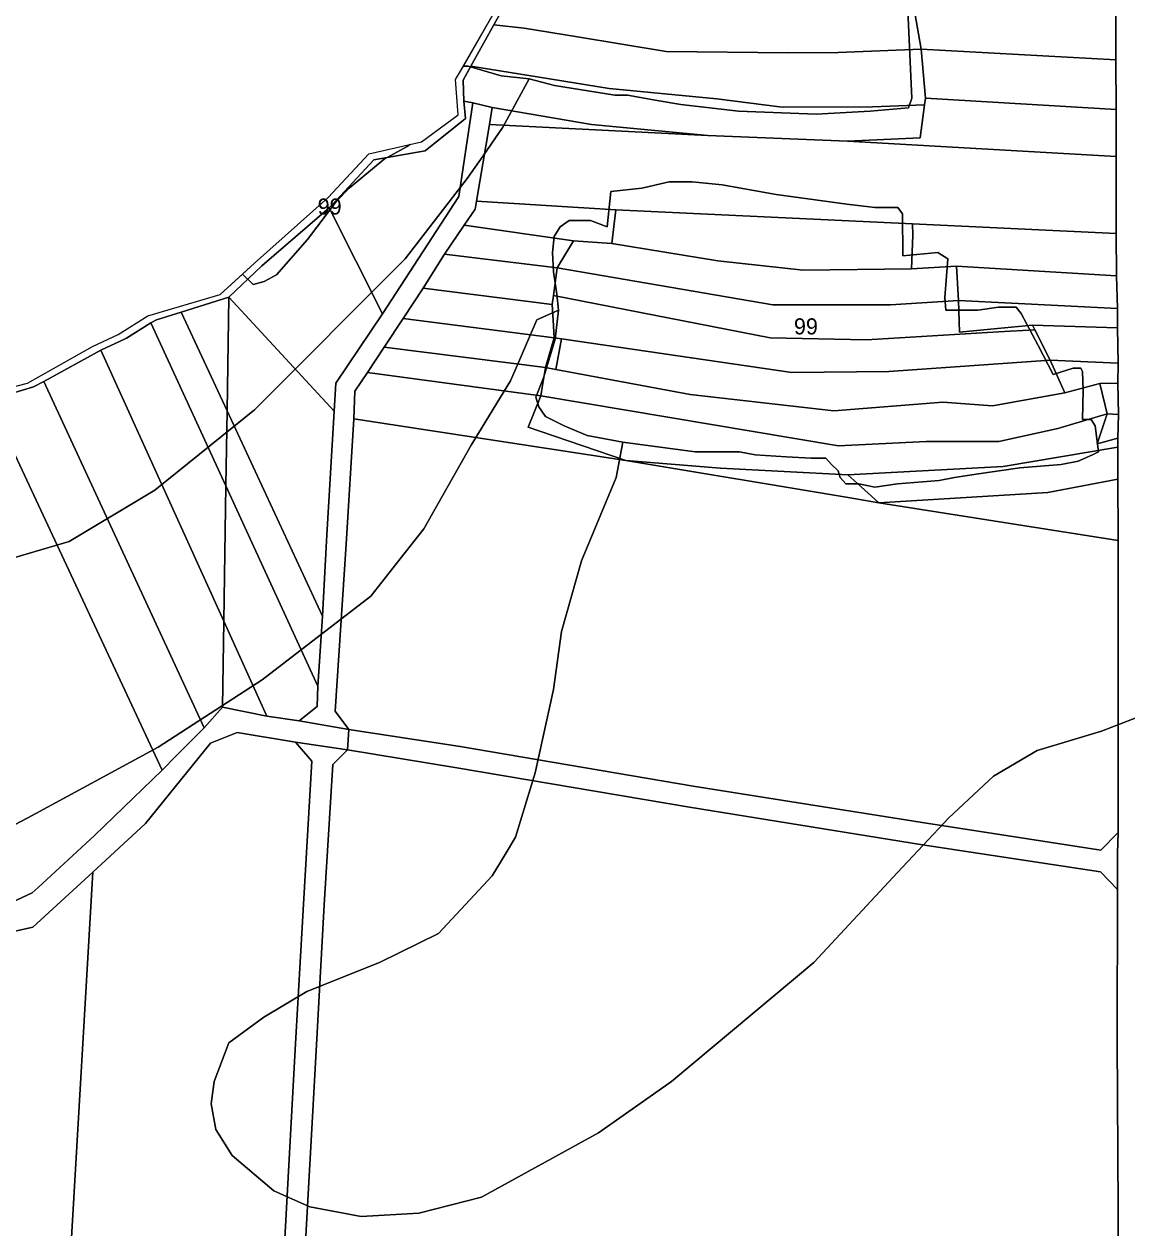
# Model space of a CAD drawing. Extents: x -541351 to -537540, y -1162694 to -1159725.
# Drawn here: x -541076 to -540733, y -1161202.6 to -1160827.9 of the extents above; entities that cross this region are included whole.
import ezdxf

# ---------------------------------------------------------------- set-up
doc = ezdxf.new("R2010")
doc.units = 0
for name, color, linetype in [('95560013', 7, 'Continuous'), ('95600013', 7, 'Continuous'), ('95610013', 7, 'Continuous'), ('95620013', 7, 'Continuous'), ('95630013', 7, 'Continuous'), ('95640013', 7, 'Continuous'), ('95660013', 7, 'Continuous')]:
    doc.layers.add(name, color=color, linetype=linetype)

msp = doc.modelspace()

# ---------------------------------------------------------------- linework, layer by layer
at = {"layer": '95560013'}
for points in [[(-541012.89, -1160948.29), (-541027.18, -1160917.57), (-541012.34, -1160912.92)], [(-540981.95, -1160988.78), (-540983.19, -1161012.15), (-541012.89, -1160948.29), (-541012.34, -1160912.92), (-540979.53, -1160948.34)], [(-541012.89, -1160948.29), (-541013.26, -1160971.68), (-541036.57, -1160920.93), (-541034.8, -1160920), (-541027.18, -1160917.57)], [(-541013.92, -1161013.74), (-541052.16, -1160929.36), (-541044.6, -1160925.92), (-541044.18, -1160925.64), (-541036.57, -1160920.93), (-541013.26, -1160971.68)], [(-541019.98, -1161046.9), (-541069.85, -1160939.12), (-541052.16, -1160929.36), (-541013.92, -1161013.74), (-541014.34, -1161040.54)], [(-541033.05, -1161060.07), (-541086.85, -1160944.98), (-541073.08, -1160940.82), (-541069.85, -1160939.12), (-541019.98, -1161046.9), (-541028.84, -1161055.79)], [(-541131.65, -1161018.53), (-541153.86, -1160970.54), (-541147.43, -1160967.41), (-541135.11, -1160960.45), (-541129.26, -1160956.98), (-541115.54, -1160952.68), (-541099.59, -1160950.61), (-541086.85, -1160944.98), (-541033.05, -1161060.07), (-541054.13, -1161080.42), (-541071.61, -1161096.64), (-541073.5, -1161098.28), (-541084.97, -1161103.63), (-541094.05, -1161099.67)], [(-541013.26, -1160971.68), (-541012.89, -1160948.29), (-540983.19, -1161012.15), (-540984.63, -1161034)], [(-540810.09, -1160976.9), (-540735.73, -1160988.61), (-540735.68, -1161079.51), (-540741.03, -1161085), (-540795.29, -1161076.62), (-540867.88, -1161065.11), (-540940.39, -1161052.8), (-540975.03, -1161047.45), (-540979.3, -1161041.8), (-540975.83, -1160989.77), (-540973.46, -1160950.74), (-540888.86, -1160963.71), (-540819.65, -1160975.28)], [(-541000.52, -1161043.31), (-541013.92, -1161013.74), (-541013.26, -1160971.68), (-540984.63, -1161034), (-540984.89, -1161040.3), (-540990.48, -1161044.81)], [(-541013.92, -1161013.74), (-541000.52, -1161043.31), (-541014.34, -1161040.54)], [(-541002.5, -1161335.95), (-541008.05, -1161340.22), (-541068.49, -1161330.02), (-541054.64, -1161091.86), (-541038.24, -1161076.76), (-541018.02, -1161051.7), (-541009.77, -1161048.36), (-540991.57, -1161051.36), (-540986.52, -1161057.36), (-540989.14, -1161101.78), (-540991.75, -1161147.06), (-540996.64, -1161238.13), (-541001.01, -1161309.69)], [(-540941.46, -1161059.38), (-540975.41, -1161053.82), (-540975.03, -1161047.45), (-540940.39, -1161052.8), (-540867.88, -1161065.11), (-540795.29, -1161076.62), (-540741.03, -1161085), (-540735.68, -1161079.51), (-540735.9, -1161086), (-540735.93, -1161097.29), (-540741.17, -1161091.8), (-540796.53, -1161083.37), (-540869, -1161071.68)], [(-540986.52, -1161057.36), (-540991.57, -1161051.36), (-540975.41, -1161053.82), (-540979.98, -1161058.32), (-540982.72, -1161102.03), (-540985.21, -1161147.42), (-540989.12, -1161218.21), (-540990.18, -1161238.48), (-540990.23, -1161238.98), (-540994.49, -1161310.1), (-540996.06, -1161337.06), (-540991.27, -1161343.31), (-541002.57, -1161341.19), (-541008.05, -1161340.22), (-541002.5, -1161335.95), (-541001.01, -1161309.69), (-540996.64, -1161238.13), (-540991.75, -1161147.06), (-540989.14, -1161101.78)], [(-540741.17, -1161091.8), (-540735.93, -1161097.29), (-540736, -1161144.39), (-540735.68, -1161196.89), (-540735.74, -1161259.49), (-540989.12, -1161218.21), (-540985.21, -1161147.42), (-540982.72, -1161102.03), (-540979.98, -1161058.32), (-540975.41, -1161053.82), (-540941.46, -1161059.38), (-540869, -1161071.68), (-540796.53, -1161083.37)], [(-541091.62, -1161326.12), (-541095.8, -1161325.34), (-541083.35, -1161111.3), (-541073.3, -1161109.03), (-541054.64, -1161091.86), (-541068.49, -1161330.02)]]:
    msp.add_lwpolyline(points, close=True, dxfattribs=at)
at = {"layer": '95600013'}
msp.add_lwpolyline([(-540736.3, -1160869.17), (-540736.28, -1160893.08), (-540799.66, -1160890.04), (-540891.91, -1160885.78), (-540935.25, -1160883), (-540931.25, -1160859.15), (-540863.38, -1160862.63), (-540819.89, -1160864.31)], close=True, dxfattribs=at)
at = {"layer": '95610013'}
for points in [[(-540798.89, -1160824.47), (-540783.37, -1160820.48), (-540764.18, -1160818.28), (-540736.36, -1160819.57), (-540736.43, -1160839.07), (-540797, -1160835.7)], [(-540795.64, -1160851.02), (-540797, -1160835.7), (-540736.43, -1160839.07), (-540736.28, -1160854.47)], [(-540951.26, -1160867.4), (-540938.73, -1160857.26), (-540939.2, -1160851.88), (-540936.46, -1160852.48), (-540940.84, -1160881.54), (-540964.49, -1160918.11), (-540981.17, -1160885.14), (-540980.33, -1160884.28), (-540967.24, -1160870.15)], [(-540736.3, -1160869.17), (-540819.89, -1160864.31), (-540797.32, -1160863.3), (-540795.91, -1160853.02), (-540795.64, -1160851.02), (-540736.28, -1160854.47)], [(-541002.06, -1160903.18), (-540981.17, -1160885.14), (-540964.49, -1160918.11), (-540979.01, -1160939.67), (-540979.53, -1160948.34), (-541012.34, -1160912.92)], [(-540939.11, -1160890.53), (-540905.15, -1160895.35), (-540910.19, -1160903.8), (-540945.23, -1160899.55)], [(-540951.85, -1160910.12), (-540945.23, -1160899.55), (-540910.19, -1160903.8), (-540911.33, -1160912.35), (-540911.72, -1160915.24)], [(-540785.33, -1160913.91), (-540785.97, -1160903.3), (-540736.22, -1160906.29), (-540735.86, -1160916.47)], [(-540911.72, -1160915.24), (-540911.45, -1160920.09), (-540911.15, -1160925.59), (-540958.07, -1160919.54), (-540951.85, -1160910.12)], [(-540773.18, -1160922.67), (-540785, -1160923.82), (-540785.33, -1160913.91), (-540735.86, -1160916.47), (-540735.87, -1160922.42), (-540762.31, -1160921.62)], [(-540958.07, -1160919.54), (-540911.15, -1160925.59), (-540911.97, -1160928.4), (-540913.85, -1160934.84), (-540963.99, -1160928.45)], [(-540761.61, -1160923.03), (-540762.31, -1160921.62), (-540735.87, -1160922.42), (-540735.69, -1160933.41), (-540756.88, -1160932.5)], [(-540915.07, -1160942.26), (-540915.29, -1160943.61), (-540969.18, -1160936.31), (-540963.99, -1160928.45), (-540913.85, -1160934.84)], [(-540735.79, -1160939.71), (-540741.43, -1160939.83), (-540752.32, -1160942.65), (-540756.88, -1160932.5), (-540735.69, -1160933.41)], [(-540973.46, -1160950.74), (-540973.09, -1160942.2), (-540969.18, -1160936.31), (-540915.29, -1160943.61), (-540919.24, -1160953.34), (-540915.61, -1160954.58), (-540888.86, -1160963.71)], [(-540741.43, -1160939.83), (-540735.79, -1160939.71), (-540735.59, -1160949.41), (-540739.08, -1160949.21)], [(-540739.08, -1160949.21), (-540735.59, -1160949.41), (-540735.79, -1160956.76), (-540742.25, -1160958.57)]]:
    msp.add_lwpolyline(points, close=True, dxfattribs=at)
at = {"layer": '95620013'}
for points in [[(-540838.25, -1160836.9), (-540876.25, -1160836.44), (-540903.88, -1160831.84), (-540920.43, -1160829.18), (-540929.88, -1160828.15), (-540927.39, -1160823.69), (-540919.49, -1160815.78), (-540908.47, -1160819.38), (-540899.74, -1160824.18), (-540849.08, -1160823.76), (-540803, -1160823.08), (-540783.37, -1160820.48), (-540798.89, -1160824.47), (-540797, -1160835.7), (-540822.78, -1160836.73)], [(-540915.84, -1160844.43), (-540937.08, -1160841.04), (-540929.88, -1160828.15), (-540920.43, -1160829.18), (-540903.88, -1160831.84), (-540876.25, -1160836.44), (-540838.25, -1160836.9), (-540822.78, -1160836.73), (-540797, -1160835.7), (-540795.64, -1160851.02), (-540795.91, -1160853.02), (-540812.07, -1160853.63), (-540840.21, -1160853.82), (-540860.48, -1160851.17), (-540894.06, -1160847.92)], [(-540840.21, -1160853.82), (-540812.07, -1160853.63), (-540795.91, -1160853.02), (-540797.32, -1160863.3), (-540819.89, -1160864.31), (-540863.38, -1160862.63), (-540899.55, -1160859.19), (-540930.39, -1160853.92), (-540936.46, -1160852.48), (-540939.2, -1160851.88), (-540939.48, -1160845.34), (-540937.08, -1160841.04), (-540915.84, -1160844.43), (-540894.06, -1160847.92), (-540860.48, -1160851.17)], [(-540899.55, -1160859.19), (-540863.38, -1160862.63), (-540931.25, -1160859.15), (-540930.39, -1160853.92)], [(-540935.25, -1160883), (-540891.91, -1160885.78), (-540893.16, -1160896.25), (-540905.15, -1160895.35), (-540939.11, -1160890.53), (-540935.75, -1160885.53)], [(-540833.7, -1160904.56), (-540860.25, -1160901.65), (-540893.16, -1160896.25), (-540891.91, -1160885.78), (-540799.66, -1160890.04), (-540799.6, -1160893.65), (-540799.98, -1160904.1)], [(-540736.28, -1160893.08), (-540736.22, -1160906.29), (-540785.97, -1160903.3), (-540799.98, -1160904.1), (-540799.6, -1160893.65), (-540799.66, -1160890.04)], [(-540910.19, -1160903.8), (-540905.15, -1160895.35), (-540893.16, -1160896.25), (-540860.25, -1160901.65), (-540833.7, -1160904.56), (-540799.98, -1160904.1), (-540785.97, -1160903.3), (-540785.33, -1160913.91), (-540806.46, -1160915.3), (-540843.14, -1160915.3)], [(-540843.91, -1160925.54), (-540911.33, -1160912.35), (-540910.19, -1160903.8), (-540843.14, -1160915.3), (-540806.46, -1160915.3), (-540785.33, -1160913.91), (-540785, -1160923.82), (-540773.18, -1160922.67), (-540762.31, -1160921.62), (-540761.61, -1160923.03), (-540772.92, -1160923.72), (-540813.93, -1160926.24)], [(-540843.91, -1160925.54), (-540813.93, -1160926.24), (-540772.92, -1160923.72), (-540761.61, -1160923.03), (-540756.88, -1160932.5), (-540807.02, -1160936.09), (-540837.23, -1160936.32), (-540908.89, -1160925.92), (-540911.15, -1160925.59), (-540911.45, -1160920.09), (-540911.72, -1160915.24), (-540911.33, -1160912.35)], [(-540910.59, -1160935.45), (-540913.85, -1160934.84), (-540911.97, -1160928.4), (-540911.15, -1160925.59), (-540908.89, -1160925.92)], [(-540807.02, -1160936.09), (-540756.88, -1160932.5), (-540752.32, -1160942.65), (-540774.82, -1160946.75), (-540790.27, -1160945.58), (-540824.11, -1160948.27), (-540868.84, -1160943.23), (-540910.59, -1160935.45), (-540908.89, -1160925.92), (-540837.23, -1160936.32)], [(-540739.08, -1160949.21), (-540754.44, -1160953.78), (-540772.83, -1160957.88), (-540795.43, -1160957.88), (-540822.71, -1160959.17), (-540915.29, -1160943.61), (-540915.07, -1160942.26), (-540913.85, -1160934.84), (-540910.59, -1160935.45), (-540868.84, -1160943.23), (-540824.11, -1160948.27), (-540790.27, -1160945.58), (-540774.82, -1160946.75), (-540752.32, -1160942.65), (-540741.43, -1160939.83)], [(-540771.43, -1160965.63), (-540819.8, -1160968.21), (-540859.38, -1160966.13), (-540888.86, -1160963.71), (-540915.61, -1160954.58), (-540919.24, -1160953.34), (-540915.29, -1160943.61), (-540822.71, -1160959.17), (-540795.43, -1160957.88), (-540772.83, -1160957.88), (-540754.44, -1160953.78), (-540739.08, -1160949.21), (-540742.25, -1160958.57), (-540735.79, -1160956.76), (-540735.79, -1160959.64)], [(-540816.82, -1160970.88), (-540819.8, -1160968.21), (-540771.43, -1160965.63), (-540735.79, -1160959.64), (-540735.78, -1160969.51), (-540757.53, -1160973.71), (-540810.09, -1160976.9)], [(-540888.86, -1160963.71), (-540859.38, -1160966.13), (-540819.8, -1160968.21), (-540816.82, -1160970.88), (-540810.09, -1160976.9), (-540819.65, -1160975.28)], [(-540735.73, -1160988.61), (-540810.09, -1160976.9), (-540757.53, -1160973.71), (-540735.78, -1160969.51), (-540735.72, -1160987.66)]]:
    msp.add_lwpolyline(points, close=True, dxfattribs=at)
at = {"layer": '95630013'}
for points in [[(-541088.68, -1160943.22), (-541074.96, -1160939.7), (-541054.72, -1160928.23), (-541046.74, -1160924.48), (-541037.53, -1160918.75), (-541015.05, -1160912.07), (-541004.31, -1160902.35), (-540981.39, -1160881.88), (-540968.74, -1160868.27), (-540952.45, -1160864.6), (-540941.04, -1160856.18), (-540941.79, -1160845.2), (-540929.37, -1160823.59)], [(-540927.39, -1160823.69), (-540929.88, -1160828.15), (-540937.08, -1160841.04), (-540939.48, -1160845.34), (-540939.2, -1160851.88), (-540938.73, -1160857.26), (-540951.26, -1160867.4), (-540967.24, -1160870.15), (-540980.33, -1160884.28), (-540981.17, -1160885.14), (-541002.06, -1160903.18), (-541012.34, -1160912.92), (-541027.18, -1160917.57), (-541034.8, -1160920), (-541036.57, -1160920.93), (-541044.18, -1160925.64), (-541044.6, -1160925.92), (-541052.16, -1160929.36), (-541069.85, -1160939.12), (-541073.08, -1160940.82), (-541086.85, -1160944.98)]]:
    msp.add_lwpolyline(points, dxfattribs=at)
at = {"layer": '95640013'}
for points in [[(-540735.74, -1161259.49), (-540735.68, -1161196.89), (-540736, -1161144.39), (-540735.93, -1161097.29), (-540735.9, -1161086), (-540735.68, -1161079.51), (-540735.73, -1160988.61), (-540735.72, -1160987.66), (-540735.78, -1160969.51), (-540735.79, -1160959.64), (-540735.79, -1160956.76), (-540735.59, -1160949.41), (-540735.79, -1160939.71), (-540735.69, -1160933.41), (-540735.87, -1160922.42), (-540735.86, -1160916.47), (-540736.22, -1160906.29), (-540736.28, -1160893.08), (-540736.3, -1160869.17), (-540736.28, -1160854.47), (-540736.43, -1160839.07), (-540736.36, -1160819.57)], [(-541084.97, -1161103.63), (-541073.5, -1161098.28), (-541071.61, -1161096.64), (-541054.13, -1161080.42), (-541033.05, -1161060.07), (-541028.84, -1161055.79), (-541019.98, -1161046.9), (-541014.34, -1161040.54), (-541000.52, -1161043.31), (-540990.48, -1161044.81), (-540975.03, -1161047.45), (-540975.41, -1161053.82), (-540991.57, -1161051.36), (-541009.77, -1161048.36), (-541018.02, -1161051.7), (-541038.24, -1161076.76), (-541054.64, -1161091.86), (-541073.3, -1161109.03), (-541083.35, -1161111.3)]]:
    msp.add_lwpolyline(points, dxfattribs=at)
msp.add_lwpolyline([(-540936.46, -1160852.48), (-540930.39, -1160853.92), (-540931.25, -1160859.15), (-540935.25, -1160883), (-540935.75, -1160885.53), (-540939.11, -1160890.53), (-540945.23, -1160899.55), (-540951.85, -1160910.12), (-540958.07, -1160919.54), (-540963.99, -1160928.45), (-540969.18, -1160936.31), (-540973.09, -1160942.2), (-540973.46, -1160950.74), (-540975.83, -1160989.77), (-540979.3, -1161041.8), (-540975.03, -1161047.45), (-540990.48, -1161044.81), (-540984.89, -1161040.3), (-540984.63, -1161034), (-540983.19, -1161012.15), (-540981.95, -1160988.78), (-540979.53, -1160948.34), (-540979.01, -1160939.67), (-540964.49, -1160918.11), (-540940.84, -1160881.54)], close=True, dxfattribs=at)
at = {"layer": '95660013'}
for points in [[(-541089.62, -1160997), (-541062, -1160989), (-541035.37, -1160973), (-541004.37, -1160948), (-540957.5, -1160901), (-540938.19, -1160876), (-540933.27, -1160868.89), (-540927.12, -1160860), (-540918.87, -1160845), (-540911, -1160847), (-540892.31, -1160850), (-540888.37, -1160850), (-540879.1, -1160851.67), (-540871.69, -1160853), (-540853.81, -1160855), (-540829.62, -1160856), (-540812.87, -1160855), (-540800.87, -1160854), (-540799.87, -1160851), (-540801.37, -1160819)], [(-540801.37, -1160819), (-540799.87, -1160851), (-540800.87, -1160854), (-540812.87, -1160855), (-540829.62, -1160856), (-540853.81, -1160855), (-540871.69, -1160853), (-540879.1, -1160851.67), (-540888.37, -1160850), (-540892.31, -1160850), (-540911, -1160847), (-540918.87, -1160845), (-540927.62, -1160844), (-540937.87, -1160841), (-540939.38, -1160841), (-540929.37, -1160823.59)], [(-541088.68, -1160943.22), (-541074.96, -1160939.7), (-541054.72, -1160928.23), (-541046.74, -1160924.48), (-541037.53, -1160918.75), (-541015.05, -1160912.07), (-541008.06, -1160905.75), (-541004.81, -1160909), (-541001.31, -1160908), (-540997.5, -1160906), (-540987.87, -1160895), (-540978.87, -1160883), (-540974.87, -1160879), (-540964, -1160870), (-540956.81, -1160866), (-540956.04, -1160865.41), (-540952.45, -1160864.6), (-540941.04, -1160856.18), (-540941.79, -1160845.2), (-540939.38, -1160841), (-540937.87, -1160841), (-540927.62, -1160844), (-540918.87, -1160845), (-540927.12, -1160860), (-540933.27, -1160868.89), (-540938.19, -1160876), (-540957.5, -1160901), (-541004.37, -1160948), (-541035.37, -1160973), (-541062, -1160989), (-541089.62, -1160997)], [(-540715.19, -1161038), (-540740.87, -1161048), (-540760.87, -1161054), (-540774.5, -1161062), (-540788.37, -1161075), (-540804.31, -1161092), (-540830.37, -1161120), (-540874.62, -1161157), (-540897.31, -1161173), (-540933.69, -1161193), (-540953.19, -1161198), (-540971.19, -1161199), (-540987.12, -1161196), (-540998.37, -1161191), (-541011.31, -1161180), (-541016.37, -1161172), (-541017.87, -1161164), (-541016.87, -1161157), (-541012.31, -1161145), (-541001.5, -1161137), (-540988.12, -1161129), (-540965.5, -1161120), (-540947.12, -1161111), (-540930.37, -1161093), (-540926.38, -1161086.33), (-540923.19, -1161081), (-540917, -1161061), (-540911.37, -1161035), (-540908.81, -1161017), (-540902.62, -1160995), (-540891.81, -1160969), (-540889.81, -1160958), (-540867.31, -1160961), (-540853.5, -1160961), (-540848.62, -1160962), (-540838.94, -1160962.56), (-540831.19, -1160963), (-540826.62, -1160963), (-540824.87, -1160965), (-540822.81, -1160967), (-540822.12, -1160969), (-540820.37, -1160971), (-540816.31, -1160971), (-540811.37, -1160972), (-540804.37, -1160971), (-540791.37, -1160970), (-540786.62, -1160969), (-540779.87, -1160968), (-540766.31, -1160966), (-540753.37, -1160965), (-540748.12, -1160964), (-540743.62, -1160962), (-540741.81, -1160961), (-540742.81, -1160953), (-540744.12, -1160951), (-540746.81, -1160951), (-540746.62, -1160942), (-540746.81, -1160936), (-540747.31, -1160935), (-540749.69, -1160935), (-540755.87, -1160937), (-540760.62, -1160928), (-540765.81, -1160918), (-540767.37, -1160916), (-540772.87, -1160916), (-540779.37, -1160917), (-540789.31, -1160917), (-540789.62, -1160913), (-540789.1, -1160906.33), (-540788.69, -1160901), (-540791.81, -1160899), (-540802.62, -1160900), (-540802.81, -1160887), (-540804.19, -1160885), (-540811.37, -1160885), (-540820.12, -1160884), (-540842.12, -1160881), (-540858.87, -1160878), (-540864.05, -1160877.44), (-540868.19, -1160877), (-540875.31, -1160877), (-540883.81, -1160879), (-540893.5, -1160880), (-540894.62, -1160891), (-540899.87, -1160889), (-540903.87, -1160889), (-540906.5, -1160889), (-540909.31, -1160891), (-540911.12, -1160894), (-540911.62, -1160899), (-540911.37, -1160905), (-540910.31, -1160912), (-540909.81, -1160917), (-540916.5, -1160920), (-540919.12, -1160926), (-540922.21, -1160933.22), (-540924.69, -1160939), (-540937, -1160959), (-540951.69, -1160985), (-540958.99, -1160994.33), (-540968.12, -1161006), (-541002, -1161032), (-541034.31, -1161053), (-541074.87, -1161075), (-541107.31, -1161092)], [(-541107.31, -1161092), (-541074.87, -1161075), (-541034.31, -1161053), (-541002, -1161032), (-540968.12, -1161006), (-540958.99, -1160994.33), (-540951.69, -1160985), (-540937, -1160959), (-540924.69, -1160939), (-540922.21, -1160933.22), (-540919.12, -1160926), (-540916.5, -1160920), (-540909.81, -1160917), (-540910.81, -1160926), (-540914.5, -1160938), (-540916.81, -1160944), (-540915.87, -1160947), (-540913.81, -1160950), (-540908, -1160953), (-540900.87, -1160956), (-540889.81, -1160958), (-540891.81, -1160969), (-540902.62, -1160995), (-540908.81, -1161017), (-540911.37, -1161035), (-540917, -1161061), (-540923.19, -1161081), (-540926.38, -1161086.33), (-540930.37, -1161093), (-540947.12, -1161111), (-540965.5, -1161120), (-540988.12, -1161129), (-541001.5, -1161137), (-541012.31, -1161145), (-541016.87, -1161157), (-541017.87, -1161164), (-541016.37, -1161172), (-541011.31, -1161180), (-540998.37, -1161191), (-540987.12, -1161196), (-540971.19, -1161199), (-540953.19, -1161198), (-540933.69, -1161193), (-540897.31, -1161173), (-540874.62, -1161157), (-540830.37, -1161120), (-540804.31, -1161092), (-540788.37, -1161075), (-540774.5, -1161062), (-540760.87, -1161054), (-540740.87, -1161048), (-540715.19, -1161038)]]:
    msp.add_lwpolyline(points, dxfattribs=at)
for points in [[(-541001.31, -1160908), (-541004.81, -1160909), (-541008.06, -1160905.75), (-541004.31, -1160902.35), (-540981.39, -1160881.88), (-540968.74, -1160868.27), (-540956.04, -1160865.41), (-540956.81, -1160866), (-540964, -1160870), (-540974.87, -1160879), (-540978.87, -1160883), (-540987.87, -1160895), (-540997.5, -1160906)], [(-540889.81, -1160958), (-540900.87, -1160956), (-540908, -1160953), (-540913.81, -1160950), (-540915.87, -1160947), (-540916.81, -1160944), (-540914.5, -1160938), (-540910.81, -1160926), (-540909.81, -1160917), (-540910.31, -1160912), (-540911.37, -1160905), (-540911.62, -1160899), (-540911.12, -1160894), (-540909.31, -1160891), (-540906.5, -1160889), (-540903.87, -1160889), (-540899.87, -1160889), (-540894.62, -1160891), (-540893.5, -1160880), (-540883.81, -1160879), (-540875.31, -1160877), (-540868.19, -1160877), (-540864.05, -1160877.44), (-540858.87, -1160878), (-540842.12, -1160881), (-540820.12, -1160884), (-540811.37, -1160885), (-540804.19, -1160885), (-540802.81, -1160887), (-540802.62, -1160900), (-540791.81, -1160899), (-540788.69, -1160901), (-540789.1, -1160906.33), (-540789.62, -1160913), (-540789.31, -1160917), (-540779.37, -1160917), (-540772.87, -1160916), (-540767.37, -1160916), (-540765.81, -1160918), (-540760.62, -1160928), (-540755.87, -1160937), (-540749.69, -1160935), (-540747.31, -1160935), (-540746.81, -1160936), (-540746.62, -1160942), (-540746.81, -1160951), (-540744.12, -1160951), (-540742.81, -1160953), (-540741.81, -1160961), (-540743.62, -1160962), (-540748.12, -1160964), (-540753.37, -1160965), (-540766.31, -1160966), (-540779.87, -1160968), (-540786.62, -1160969), (-540791.37, -1160970), (-540804.37, -1160971), (-540811.37, -1160972), (-540816.31, -1160971), (-540820.37, -1160971), (-540822.12, -1160969), (-540822.81, -1160967), (-540824.87, -1160965), (-540826.62, -1160963), (-540831.19, -1160963), (-540838.94, -1160962.56), (-540848.62, -1160962), (-540853.5, -1160961), (-540867.31, -1160961)]]:
    msp.add_lwpolyline(points, close=True, dxfattribs=at)

# ---------------------------------------------------------------- texts
for rotation, p in [(0, (-540984.69, -1160887.2)), (360, (-540836.54, -1160924.5))]:
    msp.add_text('99', height=5, rotation=rotation, dxfattribs=at).set_placement(p)

doc.saveas('drawing.dxf')
